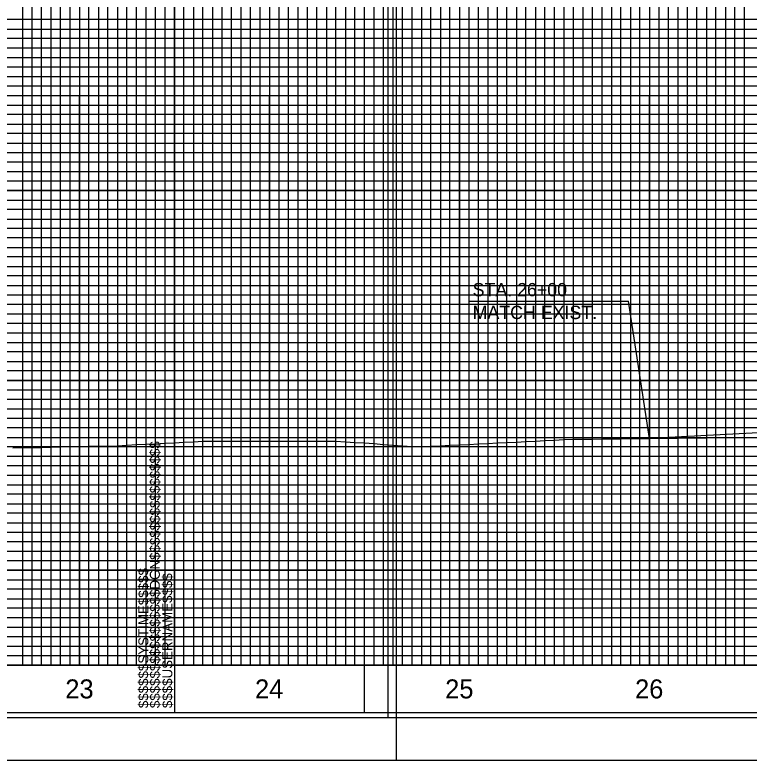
# Model space of a CAD drawing. Extents: x 2345490 to 2436403, y 465165 to 573888.
# Drawn here: x 2383032.9 to 2383419.3, y 523493.2 to 523885.7 of the extents above; entities that cross this region are included whole.
import ezdxf

# ---------------------------------------------------------------- set-up
doc = ezdxf.new("R2010")
doc.units = 0
for name, color, linetype in [('Old_Level_1', 7, 'Continuous'), ('Old_Level_18', 7, 'Continuous'), ('Old_Level_2', 7, 'Continuous'), ('Old_Level_40', 7, 'Continuous'), ('Old_Level_41', 7, 'Continuous'), ('Old_Level_42', 7, 'Continuous'), ('Old_Level_43', 7, 'Continuous'), ('Old_Level_50', 7, 'Continuous'), ('Old_Level_51', 7, 'Continuous'), ('Old_Level_57', 7, 'Continuous'), ('Old_Level_63', 7, 'Continuous')]:
    doc.layers.add(name, color=color, linetype=linetype)

msp = doc.modelspace()

# ---------------------------------------------------------------- linework, layer by layer
at = {"layer": 'Old_Level_1'}
for points in [[(2383266.799, 523659.20725), (2383271.799, 523659.46225), (2383276.799, 523659.717), (2383281.799, 523659.972), (2383286.799, 523660.227), (2383291.799, 523660.48175), (2383296.799, 523660.702), (2383301.799, 523660.959), (2383306.799, 523661.216), (2383311.799, 523661.473), (2383316.799, 523661.73), (2383321.799, 523661.987), (2383326.799, 523662.16275), (2383331.799, 523662.2185), (2383336.799, 523662.2745), (2383341.799, 523662.3305), (2383346.799, 523662.38375), (2383351.799, 523662.4395), (2383356.799, 523662.4955), (2383361.799, 523662.5515), (2383366.799, 523662.60725), (2383371.799, 523662.66325), (2383376.799, 523662.71825), (2383381.799, 523662.77425), (2383386.799, 523662.83025), (2383391.799, 523662.886), (2383396.799, 523662.942), (2383401.799, 523662.998), (2383406.799, 523663.0505), (2383411.799, 523663.04125), (2383416.799, 523663.032), (2383421.799, 523663.02275)], [(2383031.799, 523657.669), (2383036.799, 523657.7485), (2383041.799, 523657.82475), (2383046.799, 523657.8975), (2383051.799, 523657.96725), (2383056.799, 523658.18975), (2383061.799, 523658.2805), (2383066.799, 523658.35525), (2383071.799, 523658.43), (2383076.799, 523658.50475), (2383081.799, 523658.5795), (2383086.799, 523658.74775), (2383091.799, 523659.03225), (2383096.799, 523659.31675), (2383101.799, 523659.57525), (2383106.799, 523659.7475), (2383111.799, 523660.0315), (2383116.799, 523660.31575), (2383121.799, 523660.59975), (2383126.799, 523660.884), (2383131.799, 523661.168), (2383136.799, 523661.18475), (2383141.799, 523661.174), (2383146.799, 523661.239), (2383151.799, 523661.225), (2383156.799, 523661.21075), (2383161.799, 523661.1965), (2383166.799, 523661.1825), (2383171.799, 523661.16825), (2383176.799, 523661.1785), (2383181.799, 523661.16275), (2383186.799, 523661.14725), (2383191.799, 523661.1315), (2383196.799, 523661.116), (2383201.799, 523661.10025), (2383206.799, 523660.863), (2383211.799, 523660.47025), (2383216.799, 523660.24), (2383221.799, 523659.84425), (2383226.799, 523659.4485), (2383231.799, 523659.05275), (2383236.799, 523658.657), (2383241.799, 523658.26125), (2383246.799, 523658.2465), (2383251.799, 523658.499), (2383256.799, 523658.75175), (2383261.799, 523659.0045), (2383266.799, 523659.20725)]]:
    msp.add_lwpolyline(points, dxfattribs=at)
at = {"layer": 'Old_Level_18'}
msp.add_line((2383116.79875, 523518.168), (2383116.79875, 523518.168), dxfattribs=at)
msp.add_line((2383116.79875, 523518.168), (2383116.79875, 523518.168), dxfattribs=at)
for points in [[(2383216.79875, 524568.168), (2381716.79875, 524568.168), (2381716.79875, 523518.168), (2383216.79875, 523518.168)], [(2384616.79875, 524568.168), (2383116.79875, 524568.168), (2383116.79875, 523518.168), (2384616.79875, 523518.168)]]:
    msp.add_lwpolyline(points, close=True, dxfattribs=at)
at = {"layer": 'Old_Level_2'}
for p, q in [((2383271.63825, 523734.88475), (2383355.8005, 523734.88475)), ((2383366.799, 523662.60825), (2383355.8005, 523734.88475)), ((2383424.309, 523665.56825), (2383366.799, 523662.60825))]:
    msp.add_line(p, q, dxfattribs=at)
at = {"layer": 'Old_Level_40'}
msp.add_line((2383116.79875, 523518.168), (2383116.79875, 523518.168), dxfattribs=at)
msp.add_line((2383116.79875, 523518.168), (2383116.79875, 523518.168), dxfattribs=at)
msp.add_line((2383116.79875, 523518.168), (2383116.79875, 523518.168), dxfattribs=at)
msp.add_line((2383116.79875, 523518.168), (2383116.79875, 523518.168), dxfattribs=at)
at = {"layer": 'Old_Level_41'}
for p, q in [((2383216.79875, 523543.168), (2381716.79875, 523543.168)), ((2384616.79875, 523543.168), (2383116.79875, 523543.168))]:
    msp.add_line(p, q, dxfattribs=at)
for points in [[(2383166.79875, 524568.168), (2383166.79875, 523543.168), (2383216.79875, 523543.168), (2383216.79875, 524568.168)], [(2383191.79875, 523543.168), (2383191.79875, 524568.168)], [(2383241.79875, 524568.168), (2383241.79875, 523543.168), (2383291.79875, 523543.168), (2383291.79875, 524568.168)], [(2383266.79875, 524568.168), (2383266.79875, 523543.168), (2383316.79875, 523543.168), (2383316.79875, 524568.168)], [(2383341.79875, 524568.168), (2383341.79875, 523543.168), (2383391.79875, 523543.168), (2383391.79875, 524568.168)], [(2383366.79875, 524568.168), (2383366.79875, 523543.168), (2383416.79875, 523543.168), (2383416.79875, 524568.168)], [(2383041.79875, 524430.618), (2383041.79875, 523543.168), (2383091.79875, 523543.168), (2383091.79875, 524430.618)], [(2383141.79875, 524430.618), (2383141.79875, 523543.168)], [(2383216.79875, 523868.168), (2381716.79875, 523868.168), (2381716.79875, 523818.168), (2383216.79875, 523818.168)], [(2384616.79875, 523868.168), (2383116.79875, 523868.168), (2383116.79875, 523818.168), (2384616.79875, 523818.168)], [(2383216.79875, 523793.168), (2381716.79875, 523793.168), (2381716.79875, 523843.168), (2383216.79875, 523843.168)], [(2384616.79875, 523793.168), (2383116.79875, 523793.168), (2383116.79875, 523843.168), (2384616.79875, 523843.168)], [(2383216.79875, 523768.168), (2381716.79875, 523768.168), (2381716.79875, 523718.168), (2383216.79875, 523718.168)], [(2384616.79875, 523768.168), (2383116.79875, 523768.168), (2383116.79875, 523718.168), (2384616.79875, 523718.168)], [(2383216.79875, 523668.168), (2381716.79875, 523668.168), (2381716.79875, 523618.168), (2383216.79875, 523618.168)], [(2384616.79875, 523668.168), (2383116.79875, 523668.168), (2383116.79875, 523618.168), (2384616.79875, 523618.168)], [(2383216.79875, 523593.168), (2381716.79875, 523593.168), (2381716.79875, 523643.168), (2383216.79875, 523643.168)], [(2384616.79875, 523593.168), (2383116.79875, 523593.168), (2383116.79875, 523643.168), (2384616.79875, 523643.168)], [(2383216.79875, 523568.168), (2381716.79875, 523568.168)], [(2384616.79875, 523568.168), (2383116.79875, 523568.168)], [(2383154.29875, 523518.168), (2383154.29875, 523518.168)]]:
    msp.add_lwpolyline(points, dxfattribs=at)
at = {"layer": 'Old_Level_42'}
for points in [[(2383066.79875, 524430.618), (2383066.79875, 523543.168), (2383116.79875, 523543.168), (2383116.79875, 524430.618)], [(2383166.79875, 524430.618), (2383166.79875, 523543.168), (2383216.79875, 523543.168)], [(2383216.79875, 523693.168), (2381716.79875, 523693.168), (2381716.79875, 523743.168), (2383216.79875, 523743.168)], [(2384616.79875, 523693.168), (2383116.79875, 523693.168), (2383116.79875, 523743.168), (2384616.79875, 523743.168)]]:
    msp.add_lwpolyline(points, dxfattribs=at)
at = {"layer": 'Old_Level_43'}
for points in [[(2383171.79875, 524568.168), (2383171.79875, 523543.168), (2383176.79875, 523543.168), (2383176.79875, 524568.168)], [(2383181.79875, 524568.168), (2383181.79875, 523543.168), (2383186.79875, 523543.168), (2383186.79875, 524568.168)], [(2383196.79875, 524568.168), (2383196.79875, 523543.168), (2383201.79875, 523543.168), (2383201.79875, 524568.168)], [(2383206.79875, 524568.168), (2383206.79875, 523543.168), (2383211.79875, 523543.168), (2383211.79875, 524568.168)], [(2383221.79875, 524568.168), (2383221.79875, 523543.168), (2383226.79875, 523543.168), (2383226.79875, 524568.168)], [(2383231.79875, 524568.168), (2383231.79875, 523543.168), (2383236.79875, 523543.168), (2383236.79875, 524568.168)], [(2383246.79875, 524568.168), (2383246.79875, 523543.168), (2383251.79875, 523543.168), (2383251.79875, 524568.168)], [(2383256.79875, 524568.168), (2383256.79875, 523543.168), (2383261.79875, 523543.168), (2383261.79875, 524568.168)], [(2383271.79875, 524568.168), (2383271.79875, 523543.168), (2383276.79875, 523543.168), (2383276.79875, 524568.168)], [(2383281.79875, 524568.168), (2383281.79875, 523543.168), (2383286.79875, 523543.168), (2383286.79875, 524568.168)], [(2383296.79875, 524568.168), (2383296.79875, 523543.168), (2383301.79875, 523543.168), (2383301.79875, 524568.168)], [(2383306.79875, 524568.168), (2383306.79875, 523543.168), (2383311.79875, 523543.168), (2383311.79875, 524568.168)], [(2383321.79875, 524568.168), (2383321.79875, 523543.168), (2383326.79875, 523543.168), (2383326.79875, 524568.168)], [(2383331.79875, 523543.168), (2383336.79875, 523543.168), (2383336.79875, 524568.168)], [(2383331.79875, 524568.168), (2383331.79875, 523543.168)], [(2383346.79875, 524568.168), (2383346.79875, 523543.168), (2383351.79875, 523543.168), (2383351.79875, 524568.168)], [(2383356.79875, 524568.168), (2383356.79875, 523543.168), (2383361.79875, 523543.168), (2383361.79875, 524568.168)], [(2383371.79875, 524568.168), (2383371.79875, 523543.168), (2383376.79875, 523543.168), (2383376.79875, 524568.168)], [(2383381.79875, 524568.168), (2383381.79875, 523543.168), (2383386.79875, 523543.168), (2383386.79875, 524568.168)], [(2383396.79875, 524568.168), (2383396.79875, 523543.168), (2383401.79875, 523543.168), (2383401.79875, 524568.168)], [(2383406.79875, 524568.168), (2383406.79875, 523543.168), (2383411.79875, 523543.168), (2383411.79875, 524568.168)], [(2383036.79875, 524430.618), (2383036.79875, 523543.168), (2383046.79875, 523543.168), (2383046.79875, 524430.618)], [(2383051.79875, 524430.618), (2383051.79875, 523543.168), (2383056.79875, 523543.168), (2383056.79875, 524430.618)], [(2383061.79875, 524430.618), (2383061.79875, 523543.168), (2383071.79875, 523543.168), (2383071.79875, 524430.618)], [(2383076.79875, 524430.618), (2383076.79875, 523543.168), (2383081.79875, 523543.168), (2383081.79875, 524430.618)], [(2383086.79875, 524430.618), (2383086.79875, 523543.168), (2383096.79875, 523543.168), (2383096.79875, 524430.618)], [(2383101.79875, 524430.618), (2383101.79875, 523543.168)], [(2383101.79875, 523543.168), (2383106.79875, 523543.168), (2383106.79875, 524430.618)], [(2383111.79875, 524430.618), (2383111.79875, 523543.168), (2383121.79875, 523543.168), (2383121.79875, 524430.618)], [(2383126.79875, 524430.618), (2383126.79875, 523543.168), (2383131.79875, 523543.168), (2383131.79875, 524430.618)], [(2383136.79875, 524430.618), (2383136.79875, 523543.168), (2383146.79875, 523543.168), (2383146.79875, 524430.618)], [(2383151.79875, 524430.618), (2383151.79875, 523543.168), (2383156.79875, 523543.168), (2383156.79875, 524430.618)], [(2383161.79875, 524430.618), (2383161.79875, 523543.168), (2383171.79875, 523543.168)], [(2383166.79875, 523883.168), (2381766.79875, 523883.168), (2381766.79875, 523878.168), (2383166.79875, 523878.168)], [(2384566.79875, 523883.168), (2383166.79875, 523883.168), (2383166.79875, 523878.168), (2384566.79875, 523878.168)], [(2383166.79875, 523873.168), (2381766.79875, 523873.168), (2381766.79875, 523863.168), (2383166.79875, 523863.168)], [(2384566.79875, 523873.168), (2383166.79875, 523873.168), (2383166.79875, 523863.168), (2384566.79875, 523863.168)], [(2383166.79875, 523858.168), (2381766.79875, 523858.168), (2381766.79875, 523853.168), (2383166.79875, 523853.168)], [(2384566.79875, 523858.168), (2383166.79875, 523858.168), (2383166.79875, 523853.168), (2384566.79875, 523853.168)], [(2383166.79875, 523848.168), (2381766.79875, 523848.168), (2381766.79875, 523838.168), (2383166.79875, 523838.168)], [(2384566.79875, 523848.168), (2383166.79875, 523848.168), (2383166.79875, 523838.168), (2384566.79875, 523838.168)], [(2383166.79875, 523833.168), (2381766.79875, 523833.168), (2381766.79875, 523828.168), (2383166.79875, 523828.168)], [(2384566.79875, 523833.168), (2383166.79875, 523833.168), (2383166.79875, 523828.168), (2384566.79875, 523828.168)], [(2383166.79875, 523823.168), (2381766.79875, 523823.168), (2381766.79875, 523813.168), (2383166.79875, 523813.168)], [(2384566.79875, 523823.168), (2383166.79875, 523823.168), (2383166.79875, 523813.168), (2384566.79875, 523813.168)], [(2383166.79875, 523808.168), (2381766.79875, 523808.168), (2381766.79875, 523803.168), (2383166.79875, 523803.168)], [(2384566.79875, 523808.168), (2383166.79875, 523808.168), (2383166.79875, 523803.168), (2384566.79875, 523803.168)], [(2383166.79875, 523798.168), (2381766.79875, 523798.168), (2381766.79875, 523788.168), (2383166.79875, 523788.168)], [(2384566.79875, 523798.168), (2383166.79875, 523798.168), (2383166.79875, 523788.168), (2384566.79875, 523788.168)], [(2383166.79875, 523783.168), (2381766.79875, 523783.168), (2381766.79875, 523778.168), (2383166.79875, 523778.168)], [(2384566.79875, 523783.168), (2383166.79875, 523783.168), (2383166.79875, 523778.168), (2384566.79875, 523778.168)], [(2383166.79875, 523773.168), (2381766.79875, 523773.168), (2381766.79875, 523763.168), (2383166.79875, 523763.168)], [(2384566.79875, 523773.168), (2383166.79875, 523773.168), (2383166.79875, 523763.168), (2384566.79875, 523763.168)], [(2383166.79875, 523758.168), (2381766.79875, 523758.168), (2381766.79875, 523753.168), (2383166.79875, 523753.168)], [(2384566.79875, 523758.168), (2383166.79875, 523758.168), (2383166.79875, 523753.168), (2384566.79875, 523753.168)], [(2383166.79875, 523748.168), (2381766.79875, 523748.168)], [(2384566.79875, 523748.168), (2383166.79875, 523748.168)], [(2381766.79875, 523738.168), (2383166.79875, 523738.168)], [(2383166.79875, 523738.168), (2384566.79875, 523738.168)], [(2383166.79875, 523733.168), (2381766.79875, 523733.168), (2381766.79875, 523728.168), (2383166.79875, 523728.168)], [(2384566.79875, 523733.168), (2383166.79875, 523733.168), (2383166.79875, 523728.168), (2384566.79875, 523728.168)], [(2383166.79875, 523723.168), (2381766.79875, 523723.168)], [(2384566.79875, 523723.168), (2383166.79875, 523723.168)], [(2381766.79875, 523713.168), (2383166.79875, 523713.168)], [(2383166.79875, 523713.168), (2384566.79875, 523713.168)], [(2383166.79875, 523708.168), (2381766.79875, 523708.168), (2381766.79875, 523703.168), (2383166.79875, 523703.168)], [(2384566.79875, 523708.168), (2383166.79875, 523708.168), (2383166.79875, 523703.168), (2384566.79875, 523703.168)], [(2383166.79875, 523698.168), (2381766.79875, 523698.168), (2381766.79875, 523688.168), (2383166.79875, 523688.168)], [(2384566.79875, 523698.168), (2383166.79875, 523698.168), (2383166.79875, 523688.168), (2384566.79875, 523688.168)], [(2383166.79875, 523683.168), (2381766.79875, 523683.168), (2381766.79875, 523678.168), (2383166.79875, 523678.168)], [(2384566.79875, 523683.168), (2383166.79875, 523683.168), (2383166.79875, 523678.168), (2384566.79875, 523678.168)], [(2383166.79875, 523673.168), (2381766.79875, 523673.168), (2381766.79875, 523663.168), (2383166.79875, 523663.168)], [(2384566.79875, 523673.168), (2383166.79875, 523673.168), (2383166.79875, 523663.168), (2384566.79875, 523663.168)], [(2383166.79875, 523658.168), (2381766.79875, 523658.168), (2381766.79875, 523653.168), (2383166.79875, 523653.168)], [(2384566.79875, 523658.168), (2383166.79875, 523658.168), (2383166.79875, 523653.168), (2384566.79875, 523653.168)], [(2383166.79875, 523648.168), (2381766.79875, 523648.168), (2381766.79875, 523638.168), (2383166.79875, 523638.168)], [(2384566.79875, 523648.168), (2383166.79875, 523648.168), (2383166.79875, 523638.168), (2384566.79875, 523638.168)], [(2383166.79875, 523633.168), (2381766.79875, 523633.168), (2381766.79875, 523628.168), (2383166.79875, 523628.168)], [(2384566.79875, 523633.168), (2383166.79875, 523633.168), (2383166.79875, 523628.168), (2384566.79875, 523628.168)], [(2383166.79875, 523623.168), (2381766.79875, 523623.168), (2381766.79875, 523613.168), (2383166.79875, 523613.168)], [(2384566.79875, 523623.168), (2383166.79875, 523623.168), (2383166.79875, 523613.168), (2384566.79875, 523613.168)], [(2383166.79875, 523608.168), (2381766.79875, 523608.168), (2381766.79875, 523603.168), (2383166.79875, 523603.168)], [(2384566.79875, 523608.168), (2383166.79875, 523608.168), (2383166.79875, 523603.168), (2384566.79875, 523603.168)], [(2383166.79875, 523598.168), (2381766.79875, 523598.168), (2381766.79875, 523588.168), (2383166.79875, 523588.168)], [(2384566.79875, 523598.168), (2383166.79875, 523598.168), (2383166.79875, 523588.168), (2384566.79875, 523588.168)], [(2383166.79875, 523583.168), (2381766.79875, 523583.168), (2381766.79875, 523578.168), (2383166.79875, 523578.168)], [(2384566.79875, 523583.168), (2383166.79875, 523583.168), (2383166.79875, 523578.168), (2384566.79875, 523578.168)], [(2383166.79875, 523573.168), (2381766.79875, 523573.168), (2381766.79875, 523563.168), (2383166.79875, 523563.168)], [(2384566.79875, 523573.168), (2383166.79875, 523573.168), (2383166.79875, 523563.168), (2384566.79875, 523563.168)], [(2383166.79875, 523558.168), (2381766.79875, 523558.168), (2381766.79875, 523553.168), (2383166.79875, 523553.168)], [(2384566.79875, 523558.168), (2383166.79875, 523558.168), (2383166.79875, 523553.168), (2384566.79875, 523553.168)], [(2383166.79875, 523548.168), (2381766.79875, 523548.168)], [(2384566.79875, 523548.168), (2383166.79875, 523548.168)]]:
    msp.add_lwpolyline(points, dxfattribs=at)
at = {"layer": 'Old_Level_50'}
for points in [[(2383229.29875, 524570.718), (2381562.79875, 524570.718), (2381562.79875, 523515.618), (2383229.29875, 523515.618)], [(2384629.29875, 524570.718), (2382962.79875, 524570.718), (2382962.79875, 523515.618), (2384629.29875, 523515.618)]]:
    msp.add_lwpolyline(points, close=True, dxfattribs=at)
at = {"layer": 'Old_Level_51'}
for points in [[(2383233.79875, 524593.168), (2381549.79875, 524593.168), (2381549.79875, 523493.168), (2383233.79875, 523493.168)], [(2384633.79875, 524593.168), (2382949.79875, 524593.168), (2382949.79875, 523493.168), (2384633.79875, 523493.168)]]:
    msp.add_lwpolyline(points, close=True, dxfattribs=at)
at = {"layer": 'Old_Level_57'}
for p, q in [((2381716.79925, 523843.16825), (2384066.79875, 523843.16825)), ((2383066.79875, 523543.16825), (2383066.79875, 523843.16825)), ((2383066.79875, 523543.26825), (2383066.79875, 523843.16825)), ((2383166.79875, 523543.16825), (2383166.79875, 523843.16825)), ((2383166.79875, 523543.26825), (2383166.79875, 523843.16825)), ((2383266.79875, 523543.16825), (2383266.79875, 523843.16825)), ((2383266.79875, 523543.26825), (2383266.79875, 523843.16825)), ((2383366.79875, 523543.16825), (2383366.79875, 523843.16825)), ((2383366.79875, 523543.26825), (2383366.79875, 523843.16825)), ((2381716.79925, 523793.16825), (2384066.79875, 523793.16825)), ((2381716.79925, 523743.16825), (2384066.79875, 523743.16825)), ((2381716.79925, 523693.16825), (2384066.79875, 523693.16825)), ((2381716.79925, 523643.16825), (2384066.79875, 523643.16825)), ((2381716.799, 523593.16825), (2384066.79875, 523593.16825)), ((2381716.79925, 523543.16825), (2384066.79875, 523543.16825))]:
    msp.add_line(p, q, dxfattribs=at)
at = {"layer": 'Old_Level_63'}
msp.add_line((2381766.79875, 523543.168), (2383942.32375, 523543.168), dxfattribs=at)

# ---------------------------------------------------------------- texts
at = {"layer": 'Old_Level_1'}
for s, p in [('23', (2383059.408, 523525.668)), ('24', (2383159.2505, 523525.668)), ('25', (2383259.343, 523525.668)), ('26', (2383359.284, 523525.668))]:
    msp.add_text(s, height=10.000001, dxfattribs=at).set_placement(p)
at = {"layer": 'Old_Level_2'}
for s, height, p in [('STA. 26+00', 7.000001, (2383273.78675, 523737.4545)), ('MATCH EXIST.', 7.0000005, (2383273.78675, 523725.4545))]:
    msp.add_text(s, height=height, dxfattribs=at).set_placement(p)
at = {"layer": 'Old_Level_41'}
for s, p in [('$$$$$$$$$$$$$$$$DGN$$$$$$$$$$$$$$$$', (2383109.14875, 523520.5305)), ('$$$$$$SYSTIME$$$$$', (2383103.09875, 523520.5305)), ('$$$$USERNAME$$$$', (2383115.72375, 523520.543))]:
    msp.add_text(s, height=5.25, rotation=90, dxfattribs=at).set_placement(p)

doc.saveas('drawing.dxf')
